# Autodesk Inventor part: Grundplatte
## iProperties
Created: 2007-03
Part Number: Grundplatte
Document SubType Name: Modeling
Designer: Benno
Manufacturer: Standard
Standards Organization: Custom
Author: Benno
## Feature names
1. Extrusion1
2. Fase1 [Chamfer]
3. Fase2 [Chamfer]
4. Rundung1 [Fillet]
5. Bohrung1 [Hole]
6. Bohrung2 [Hole]
7. Bohrung3 [Hole]
8. Bohrung4 [Hole]
9. Bohrung6 [Hole]
10. Fase3 [Chamfer]
